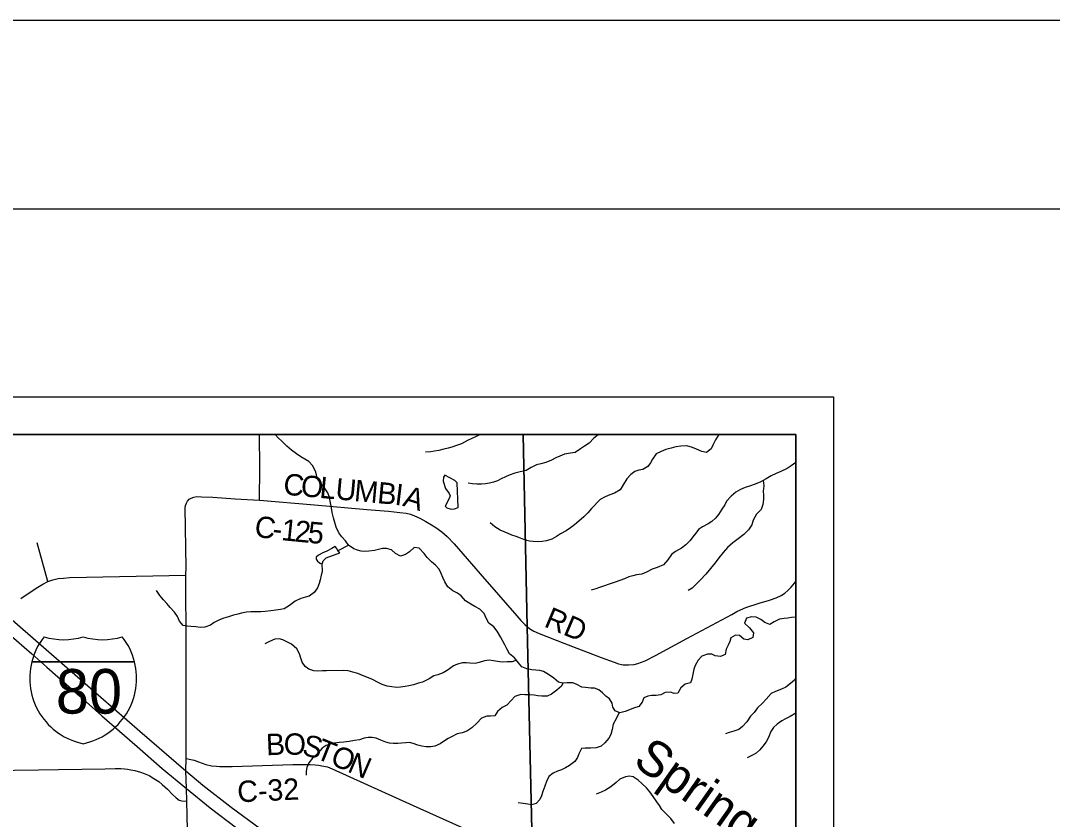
# Model space of a CAD drawing. Extents: x 0 to 34, y 0 to 22.
# Drawn here: x 6.839 to 9.582, y 19.877 to 22 of the extents above; entities that cross this region are included whole.
import ezdxf

# ---------------------------------------------------------------- set-up
doc = ezdxf.new("R2010")
doc.units = 0
for name, color, linetype in [('Default', 7, 'Continuous'), ('GM_X_County_Road', 7, 'Continuous'), ('GM_X_County_Road_Text', 7, 'Continuous'), ('GM_X_Interstate_Location', 7, 'Continuous'), ('GM_X_Interstate_Route', 7, 'Continuous'), ('GM_X_Interstate_Shield', 7, 'Continuous'), ('GM_X_Minor_Lake', 7, 'Continuous'), ('GM_X_Minor_River', 7, 'Continuous'), ('GM_X_Minor_River_Text', 7, 'Continuous'), ('GM_X_Township_Road', 7, 'Continuous'), ('SH_Border', 7, 'Continuous'), ('SH_Cut_Line', 7, 'Continuous'), ('SH_Data', 7, 'Continuous')]:
    doc.layers.add(name, color=color, linetype=linetype)

msp = doc.modelspace()

# ---------------------------------------------------------------- linework, layer by layer
at = {"layer": 'Default'}
msp.add_lwpolyline([(8.1995, 19.7718), (8.1859, 20.3892), (8.1749, 20.9), (3.2826, 20.9)], dxfattribs=at)
msp.add_lwpolyline([(8.9, 15.9304), (8.9, 20.9), (8.1749, 20.9), (8.1859, 20.3892), (8.1995, 19.7718), (8.2061, 19.4737), (8.2069, 19.4369), (8.2195, 18.875), (8.2216, 18.8361), (8.2229, 18.8136), (8.2232, 18.7798), (8.2237, 18.7271), (8.2254, 18.6464), (8.2283, 18.4271), (8.2338, 18.0126), (8.2361, 17.5877), (8.2392, 17.3521), (8.2417, 17.2403), (8.2434, 16.7876), (8.2536, 16.1438), (8.2582, 15.9227), (8.4608, 15.9241), (8.569, 15.9256)], close=True, dxfattribs=at)
at = {"layer": 'GM_X_County_Road'}
for points in [[(7.2787, 20.0387), (7.2789, 20.1292), (7.2787, 20.3326), (7.2785, 20.5259), (7.2791, 20.5462), (7.2766, 20.7047), (7.2775, 20.7109), (7.2801, 20.7176), (7.2828, 20.7229), (7.2874, 20.7279), (7.2927, 20.7309), (7.2994, 20.7335), (7.3073, 20.7349), (7.3199, 20.7346), (7.3503, 20.7335), (7.4098, 20.7293), (7.4741, 20.7253)], [(7.4741, 20.7253), (7.6206, 20.7132), (7.7597, 20.7005), (7.8166, 20.6959), (7.8475, 20.6929), (7.8636, 20.6906), (7.8754, 20.6881), (7.8864, 20.6842), (7.9007, 20.6777), (7.9159, 20.669), (7.9309, 20.6602), (7.9426, 20.6528), (7.959, 20.6411), (7.9728, 20.6291), (7.9915, 20.6098), (8.0608, 20.5294), (8.1585, 20.4179), (8.1688, 20.4057), (8.1792, 20.3948), (8.1861, 20.3886), (8.1914, 20.3848)], [(8.1914, 20.3848), (8.1944, 20.3826), (8.2036, 20.3773), (8.2179, 20.3711), (8.2827, 20.3455), (8.3819, 20.3071), (8.4165, 20.2946), (8.4287, 20.2907), (8.4407, 20.2882), (8.4552, 20.2875), (8.4699, 20.2886), (8.4799, 20.2914), (8.4997, 20.2985), (8.5268, 20.3124), (8.61, 20.3577), (8.7293, 20.422), (8.7432, 20.4296), (8.7524, 20.434), (8.7669, 20.4404), (8.8021, 20.4517), (8.8296, 20.4596), (8.8478, 20.466), (8.8604, 20.4722), (8.8706, 20.4784), (8.8786, 20.4854), (8.8871, 20.4939), (8.8961, 20.5045), (8.9, 20.5095)], [(7.2805, 19.9253), (7.2801, 19.959), (7.2785, 20.0062), (7.2787, 20.0387)], [(7.2787, 20.0387), (7.2914, 20.0361), (7.3003, 20.0341), (7.3119, 20.0299), (7.3218, 20.0262), (7.3317, 20.0232), (7.3469, 20.0198), (7.3596, 20.0183), (7.369, 20.0175), (7.4017, 20.0179), (7.563, 20.0232), (7.5984, 20.023), (7.6086, 20.0228), (7.6222, 20.0221), (7.6305, 20.0212), (7.6401, 20.0198), (7.6547, 20.0163), (7.6676, 20.011), (7.8823, 19.9136), (8.1094, 19.812), (8.1997, 19.7712), (8.2034, 19.7696)], [(6.6953, 20.0065), (6.8865, 20.0091), (6.9395, 20.0093), (7.0639, 20.0117), (7.0906, 20.0121), (7.1059, 20.0119), (7.1152, 20.0115), (7.123, 20.0107), (7.1319, 20.0091), (7.1423, 20.0073), (7.158, 20.0029), (7.1671, 19.9993), (7.1805, 19.9936), (7.1936, 19.986), (7.2061, 19.9779), (7.2157, 19.9701), (7.2296, 19.9578), (7.2431, 19.9431), (7.2522, 19.9343), (7.2602, 19.9285), (7.2676, 19.9264), (7.2805, 19.9253)], [(7.3109, 18.7479), (7.3061, 18.9361), (7.3003, 19.1331), (7.296, 19.3266), (7.2915, 19.4531), (7.2874, 19.6581), (7.2805, 19.9253)]]:
    msp.add_lwpolyline(points, dxfattribs=at)
at = {"layer": 'GM_X_Interstate_Route'}
for points in [[(6.7966, 20.4252), (6.9486, 20.2925), (7.156, 20.1111), (7.2785, 20.0062), (7.3237, 19.9679), (7.3987, 19.9098), (7.4761, 19.8527), (7.5666, 19.7895), (7.7006, 19.7055), (7.763, 19.6693)], [(6.7749, 20.3983), (6.8079, 20.3699), (6.8685, 20.317), (6.9085, 20.2814), (6.9964, 20.2046), (7.0553, 20.1519), (7.149, 20.0706), (7.2156, 20.0127), (7.2801, 19.959), (7.343, 19.9077), (7.4133, 19.8545), (7.4638, 19.8177), (7.5083, 19.7871), (7.5915, 19.7321), (7.6978, 19.6669), (7.77, 19.6256)]]:
    msp.add_lwpolyline(points, dxfattribs=at)
at = {"layer": 'GM_X_Interstate_Shield'}
for p, q in [((6.8687, 20.2958), (7.142, 20.2958)), ((7.142, 20.2958), (6.8687, 20.2958)), ((7.142, 20.2958), (6.8687, 20.2958))]:
    msp.add_line(p, q, dxfattribs=at)
for centre, start, end in [((7.0409, 20.2523), 141.669, 165.8066), ((6.9535, 20.5322), 253.0091, 286.9909), ((7.0572, 20.5322), 253.0091, 286.9909), ((6.9698, 20.2523), 14.1934, 38.331), ((7.0409, 20.2523), 165.8066, 258.463), ((6.9698, 20.2523), 281.537, 14.1934)]:
    msp.add_arc(centre, 0.1776, start, end, dxfattribs=at)
at = {"layer": 'GM_X_Minor_Lake'}
for points in [[(7.9993, 20.7717), (7.9936, 20.7774), (7.9669, 20.7919), (7.9628, 20.7869), (7.9621, 20.7763), (7.9684, 20.7566), (7.9787, 20.7434), (7.981, 20.7366), (7.9784, 20.7301), (7.968, 20.7099), (7.9722, 20.705), (7.9832, 20.702), (7.9923, 20.7029), (8.0025, 20.7056)], [(8.0025, 20.7056), (7.9993, 20.7717)], [(7.6874, 20.5852), (7.6832, 20.5894), (7.6798, 20.5973), (7.6752, 20.6022), (7.6665, 20.5972), (7.6533, 20.5898), (7.642, 20.5855), (7.6306, 20.5794), (7.6246, 20.574), (7.6247, 20.569), (7.6285, 20.563), (7.6327, 20.56), (7.6365, 20.557), (7.6418, 20.5582), (7.6433, 20.5643), (7.647, 20.5681), (7.6515, 20.5719)], [(7.6515, 20.5719), (7.6874, 20.5852)]]:
    msp.add_lwpolyline(points, dxfattribs=at)
at = {"layer": 'GM_X_Minor_River'}
for points in [[(7.6739, 20.666), (7.6711, 20.6781), (7.6676, 20.6929), (7.6659, 20.7051), (7.6632, 20.718), (7.6604, 20.7328), (7.6557, 20.7453), (7.6465, 20.7581), (7.6358, 20.7717), (7.6285, 20.7822), (7.6258, 20.7928), (7.623, 20.8027), (7.6149, 20.8178), (7.6054, 20.828), (7.5947, 20.8347), (7.584, 20.8407), (7.5726, 20.8482), (7.5588, 20.8587), (7.5466, 20.8688), (7.5332, 20.8824), (7.5237, 20.891), (7.5161, 20.9)], [(8.0611, 20.9), (8.0604, 20.8996), (8.0498, 20.8945), (8.0388, 20.8895), (8.0271, 20.8837), (8.0109, 20.8755), (7.9981, 20.8705), (7.9856, 20.8662), (7.9758, 20.8638), (7.9644, 20.8607), (7.9512, 20.8579), (7.9391, 20.8555), (7.9292, 20.8542), (7.9156, 20.853)], [(8.3761, 20.9), (8.3746, 20.8988), (8.3626, 20.8903), (8.3505, 20.8773), (8.3381, 20.8688), (8.3275, 20.8622), (8.3129, 20.8522), (8.3004, 20.8502), (8.2852, 20.8474), (8.2724, 20.8427), (8.2622, 20.8377), (8.2501, 20.8322), (8.235, 20.826), (8.2221, 20.8217), (8.21, 20.8193), (8.1964, 20.8123), (8.1825, 20.8046), (8.167, 20.801), (8.153, 20.7975), (8.1379, 20.7916), (8.1277, 20.7874), (8.1164, 20.7819), (8.1065, 20.7769), (8.0963, 20.7734), (8.0854, 20.7706), (8.0744, 20.769), (8.0645, 20.7678), (8.0516, 20.7684), (8.0399, 20.7691), (8.0285, 20.7708)], [(8.6953, 20.9), (8.6859, 20.8858), (8.68, 20.8732), (8.6744, 20.8617), (8.6623, 20.8525), (8.6498, 20.8547), (8.6357, 20.861), (8.6251, 20.8654), (8.6103, 20.8695), (8.5943, 20.8693), (8.5811, 20.8669), (8.5686, 20.8638), (8.5546, 20.8602), (8.5414, 20.8552), (8.5286, 20.8489), (8.5188, 20.8348), (8.5132, 20.8245), (8.5061, 20.8149), (8.4929, 20.8068), (8.4827, 20.8048), (8.4717, 20.8017), (8.4608, 20.7936), (8.4507, 20.7821), (8.441, 20.7664), (8.4331, 20.7534), (8.418, 20.7445), (8.4052, 20.7399), (8.3927, 20.734), (8.3795, 20.7271), (8.3566, 20.7037), (8.3472, 20.6922), (8.3363, 20.6815), (8.3228, 20.6695), (8.3111, 20.6599), (8.3006, 20.6519), (8.2893, 20.6438), (8.2745, 20.6356), (8.2636, 20.6291), (8.2508, 20.6221), (8.2372, 20.6178), (8.2251, 20.6158), (8.2126, 20.6145), (8.2016, 20.6152), (8.1917, 20.6162), (8.1811, 20.6196), (8.1681, 20.6244), (8.156, 20.6288), (8.1449, 20.6329), (8.1354, 20.6366), (8.1244, 20.6414), (8.1134, 20.6459), (8.1, 20.6549), (8.0874, 20.665)], [(8.9, 20.8256), (8.8874, 20.817), (8.8765, 20.8101), (8.8603, 20.8016), (8.8471, 20.7961), (8.8346, 20.7903), (8.821, 20.7822), (8.8052, 20.7737), (8.7893, 20.7667), (8.7791, 20.7636), (8.7647, 20.7589), (8.7527, 20.7538), (8.7402, 20.7469), (8.7278, 20.7365), (8.7154, 20.7231), (8.7109, 20.7131), (8.7031, 20.702), (8.6945, 20.6871), (8.6866, 20.6776), (8.6768, 20.6684), (8.667, 20.6629), (8.6519, 20.6548), (8.6414, 20.6475), (8.6339, 20.6376), (8.6264, 20.628), (8.6193, 20.6184), (8.6076, 20.6065), (8.5959, 20.5977), (8.5801, 20.5895), (8.5692, 20.5807), (8.5598, 20.5669), (8.5482, 20.5539), (8.5312, 20.5465), (8.5176, 20.5422), (8.5025, 20.5337), (8.49, 20.5287), (8.476, 20.5266), (8.4662, 20.5246), (8.4556, 20.5219), (8.4439, 20.5164), (8.4322, 20.5121), (8.4197, 20.5078), (8.4034, 20.502), (8.3883, 20.4969), (8.3781, 20.493), (8.3679, 20.4895), (8.3558, 20.4863)], [(8.8132, 20.778), (8.8147, 20.7639), (8.813, 20.7498), (8.8134, 20.7384), (8.8135, 20.7274), (8.8118, 20.7137), (8.8077, 20.7004), (8.7953, 20.6881), (8.7863, 20.6724), (8.7827, 20.6603), (8.7744, 20.6465), (8.7613, 20.6338), (8.7462, 20.6227), (8.7327, 20.6119), (8.7184, 20.6), (8.7063, 20.5866), (8.6955, 20.5724), (8.6854, 20.559), (8.673, 20.5441), (8.6602, 20.5288), (8.6463, 20.5138), (8.6369, 20.5038), (8.6245, 20.4919), (8.614, 20.4858)], [(8.6996, 20.3099), (8.6856, 20.3117), (8.6761, 20.3158), (8.6647, 20.3164), (8.6503, 20.3106), (8.6398, 20.2998), (8.6324, 20.2865), (8.629, 20.2765), (8.6257, 20.2632), (8.6236, 20.2495), (8.6195, 20.24), (8.6055, 20.2368), (8.5942, 20.2264), (8.5864, 20.2127), (8.5761, 20.2118), (8.5666, 20.2152), (8.5526, 20.2143), (8.5413, 20.2085), (8.5288, 20.2064), (8.5159, 20.2063), (8.5061, 20.2047), (8.4959, 20.2004), (8.4911, 20.189), (8.4824, 20.1775), (8.4685, 20.1728), (8.4579, 20.1685), (8.4458, 20.1639), (8.4318, 20.1603), (8.4192, 20.1655), (8.4135, 20.1753), (8.4119, 20.1863), (8.4049, 20.1973), (8.395, 20.2044), (8.3855, 20.2131), (8.3759, 20.2213), (8.3645, 20.2254), (8.3547, 20.2261), (8.341, 20.2274), (8.3311, 20.2289), (8.3178, 20.2356), (8.3068, 20.2404), (8.2916, 20.2403), (8.2802, 20.2394), (8.2689, 20.2416), (8.2566, 20.2521), (8.2421, 20.2622), (8.2288, 20.2701), (8.2193, 20.2726), (8.2083, 20.2741), (8.1977, 20.2747), (8.1848, 20.2769), (8.1718, 20.2824), (8.1623, 20.293), (8.1519, 20.3066), (8.1389, 20.3167), (8.1312, 20.3303), (8.1258, 20.3413), (8.1151, 20.3625), (8.1062, 20.3776), (8.0966, 20.3889), (8.0833, 20.3982), (8.0763, 20.4119), (8.0713, 20.4244), (8.0595, 20.436), (8.0465, 20.4431), (8.0355, 20.4491), (8.0221, 20.4581), (8.0102, 20.4716), (8.0007, 20.4784), (7.9878, 20.4847), (7.9748, 20.4949), (7.9671, 20.5088), (7.9617, 20.5202), (7.9574, 20.5304), (7.9516, 20.5418), (7.9417, 20.5531), (7.9314, 20.5617), (7.9199, 20.5734), (7.9119, 20.5839), (7.8985, 20.5979), (7.8856, 20.5993), (7.8724, 20.5885), (7.8626, 20.5812), (7.849, 20.5769), (7.836, 20.584), (7.825, 20.5934), (7.8113, 20.597), (7.8011, 20.5966), (7.7901, 20.5942), (7.7795, 20.5918), (7.7651, 20.5898), (7.7545, 20.5889), (7.7439, 20.5903), (7.7344, 20.5925), (7.7245, 20.5958), (7.7111, 20.6063), (7.7031, 20.6173), (7.6928, 20.6282), (7.6847, 20.6391), (7.6781, 20.6535), (7.6739, 20.666)], [(7.7116, 20.606), (7.6826, 20.5907)], [(7.6402, 20.5578), (7.6405, 20.5354), (7.6383, 20.5258), (7.6357, 20.5137), (7.6324, 20.5038), (7.6284, 20.4927), (7.6197, 20.4797), (7.6062, 20.4704), (7.5963, 20.4677), (7.5839, 20.4645), (7.5691, 20.4572), (7.5541, 20.4453), (7.5398, 20.4364), (7.5299, 20.4348), (7.5174, 20.4327), (7.5042, 20.4311), (7.489, 20.4298), (7.478, 20.4289), (7.4644, 20.4288), (7.4511, 20.4283), (7.4394, 20.4274), (7.4265, 20.4254), (7.4167, 20.4227), (7.4053, 20.4195), (7.3913, 20.4156), (7.3792, 20.412), (7.3679, 20.4078), (7.354, 20.4004), (7.3434, 20.3935), (7.3287, 20.388), (7.3162, 20.3875), (7.3048, 20.3885), (7.2919, 20.3896), (7.2816, 20.3902), (7.2714, 20.392), (7.2618, 20.4037), (7.256, 20.4162), (7.2483, 20.4279), (7.2369, 20.4399), (7.2277, 20.4505), (7.2189, 20.4603), (7.2093, 20.4724), (7.2005, 20.4852)], [(8.9, 20.4146), (8.8886, 20.4132), (8.8788, 20.4115), (8.869, 20.4114), (8.8561, 20.409), (8.8425, 20.4021), (8.8304, 20.3951), (8.8171, 20.4003), (8.8068, 20.4082), (8.7943, 20.4145), (8.7821, 20.4156), (8.7689, 20.412), (8.7629, 20.399), (8.7763, 20.3866), (8.787, 20.373), (8.7852, 20.3609), (8.7724, 20.3547), (8.7618, 20.3561), (8.7496, 20.3662), (8.7397, 20.3669), (8.7269, 20.3599), (8.7247, 20.3497), (8.7202, 20.3401), (8.7146, 20.3298), (8.7121, 20.315), (8.6996, 20.3099)], [(8.1571, 20.2998), (8.146, 20.2959), (8.1323, 20.2954), (8.119, 20.2949), (8.1069, 20.2966), (8.0963, 20.2988), (8.0845, 20.2999), (8.0724, 20.2986), (8.0584, 20.2939), (8.0471, 20.2915), (8.0334, 20.2925), (8.0239, 20.2932), (8.0141, 20.2931), (8.0004, 20.2899), (7.9899, 20.2853), (7.9756, 20.2745), (7.9624, 20.2664), (7.948, 20.2613), (7.9378, 20.2589), (7.925, 20.2505), (7.9076, 20.2419), (7.8966, 20.2388), (7.8838, 20.2349), (7.8709, 20.2317), (7.8611, 20.2301), (7.849, 20.2281), (7.8387, 20.228), (7.8255, 20.229), (7.8133, 20.2312), (7.8, 20.236), (7.7894, 20.2412), (7.7745, 20.249), (7.7597, 20.255), (7.7483, 20.2598), (7.7357, 20.2646), (7.7224, 20.2687), (7.7095, 20.2716), (7.6981, 20.2726), (7.6526, 20.2722), (7.6416, 20.2717), (7.628, 20.2708), (7.6181, 20.2715), (7.6048, 20.2763), (7.5953, 20.2834), (7.5876, 20.2951), (7.5841, 20.3053), (7.5802, 20.3175), (7.5729, 20.3303), (7.5588, 20.3427), (7.5489, 20.3483), (7.5363, 20.3539), (7.526, 20.3568), (7.5147, 20.3563), (7.5003, 20.3501), (7.4879, 20.3439)], [(8.9, 20.2532), (8.8958, 20.2472), (8.8856, 20.238), (8.8736, 20.2287), (8.8615, 20.2229), (8.8456, 20.2174), (8.8339, 20.2113), (8.8212, 20.1967), (8.811, 20.1856), (8.7982, 20.1733), (8.7889, 20.1614), (8.7791, 20.1511), (8.7697, 20.1365), (8.7581, 20.1235), (8.7483, 20.1162), (8.7351, 20.1115), (8.7226, 20.1084), (8.7128, 20.1048)], [(8.2807, 20.2394), (8.2773, 20.2314), (8.2645, 20.2203), (8.2502, 20.2102), (8.2388, 20.2048), (8.2244, 20.2043), (8.2142, 20.2057), (8.204, 20.2075), (8.193, 20.2082), (8.1793, 20.2084), (8.1687, 20.2091), (8.1532, 20.204), (8.1427, 20.1933), (8.1314, 20.1806), (8.1189, 20.1744), (8.1065, 20.1637), (8.0998, 20.1526), (8.0881, 20.1517), (8.0782, 20.1516), (8.0642, 20.1458), (8.0518, 20.1327), (8.0387, 20.1205), (8.0255, 20.1116), (8.013, 20.1073), (7.9998, 20.1041), (7.9862, 20.0975), (7.976, 20.0921), (7.9662, 20.0856), (7.9541, 20.0782), (7.9398, 20.0713), (7.9296, 20.0696), (7.9171, 20.0699), (7.9053, 20.0717), (7.895, 20.0746), (7.8825, 20.0787), (7.873, 20.0813), (7.8631, 20.0808), (7.8518, 20.0799), (7.8419, 20.0787), (7.8306, 20.0786), (7.8196, 20.08), (7.8097, 20.0826), (7.7967, 20.0877), (7.7846, 20.093), (7.7739, 20.0951), (7.7633, 20.095), (7.7527, 20.093), (7.7399, 20.0887), (7.7266, 20.0863), (7.7126, 20.0843), (7.6986, 20.0826), (7.6861, 20.081), (7.6725, 20.0793), (7.6623, 20.077), (7.6513, 20.0731), (7.6411, 20.0665), (7.6299, 20.0542), (7.6152, 20.0397), (7.6051, 20.0274), (7.5995, 20.0152), (7.5981, 20.0053), (7.5978, 19.995)], [(8.4302, 20.161), (8.4225, 20.1446), (8.4142, 20.1301), (8.4117, 20.116), (8.408, 20.1027), (8.4024, 20.0928), (8.3923, 20.0805), (8.3821, 20.0721), (8.3689, 20.0674), (8.3541, 20.0665), (8.3401, 20.0667), (8.3303, 20.0655), (8.3232, 20.0514), (8.3191, 20.0414), (8.312, 20.0311), (8.2981, 20.02), (8.2871, 20.0138), (8.2773, 20.0091), (8.2664, 20.0052), (8.2543, 20.0002), (8.243, 19.9909), (8.2366, 19.9776), (8.2322, 19.965), (8.227, 19.9513), (8.2241, 19.9398), (8.2192, 19.9303), (8.2091, 19.9196), (8.197, 19.9156), (8.1875, 19.9175), (8.1746, 19.9192), (8.1617, 19.921)], [(8.9, 20.1591), (8.8845, 20.1509), (8.8724, 20.1444), (8.8626, 20.139), (8.8505, 20.1305), (8.8404, 20.1216), (8.8336, 20.1106), (8.8273, 20.0945), (8.8206, 20.0831), (8.812, 20.072), (8.8045, 20.062), (8.794, 20.0532), (8.7842, 20.0474), (8.7702, 20.0404)], [(8.5776, 19.8665), (8.5673, 19.8793), (8.5573, 19.8902), (8.5436, 19.9034), (8.5374, 19.914), (8.5305, 19.9238), (8.5205, 19.9377), (8.5117, 19.9506), (8.5029, 19.9607), (8.4903, 19.9724), (8.4807, 19.981), (8.4678, 19.99), (8.4575, 19.9915), (8.4469, 19.9898), (8.4318, 19.984), (8.422, 19.9752), (8.4077, 19.964), (8.3942, 19.9544), (8.3824, 19.9497), (8.3692, 19.9439)]]:
    msp.add_lwpolyline(points, dxfattribs=at)
at = {"layer": 'GM_X_Township_Road'}
msp.add_line((6.9115, 20.5095), (6.8834, 20.6118), dxfattribs=at)
for points in [[(7.4741, 20.7253), (7.475, 20.8109), (7.4745, 20.9)], [(6.8394, 20.4642), (6.8808, 20.4916), (6.8977, 20.5019), (6.9115, 20.5095), (6.9248, 20.5139), (6.9389, 20.5169), (6.9534, 20.5185), (6.9695, 20.5197), (7.2785, 20.5259)]]:
    msp.add_lwpolyline(points, dxfattribs=at)
at = {"layer": 'SH_Border'}
msp.add_lwpolyline([(1.5, 21.5), (33.5, 21.5), (33.5, 0.5), (1.5, 0.5)], close=True, dxfattribs=at)
at = {"layer": 'SH_Cut_Line'}
for points in [[(0, 0), (34, 0), (34, 22), (0, 22)], [(3.2807, 14.1), (8.9, 14.1), (8.9, 20.9), (3.2826, 20.9), (3.2843, 20.6124), (3.2845, 20.5998), (3.2888, 19.8918), (3.2901, 19.68), (3.2904, 19.1173), (3.2907, 18.4315), (3.2837, 17.3796), (3.2835, 17.0107), (3.2832, 16.3898), (3.2829, 15.8433), (3.2815, 15.7537), (3.2811, 15.7294), (3.2832, 14.8896), (3.2841, 14.501), (3.2822, 14.2781), (3.2808, 14.1155)]]:
    msp.add_lwpolyline(points, close=True, dxfattribs=at)
at = {"layer": 'SH_Data'}
for p, q in [((2, 21), (9, 21)), ((9, 21), (9, 14)), ((2.1, 20.9), (8.9, 20.9)), ((8.9, 20.9), (8.9, 14.1))]:
    msp.add_line(p, q, dxfattribs=at)

# ---------------------------------------------------------------- texts
at = {"layer": 'GM_X_County_Road_Text'}
for s, height, rotation, p in [('C', 0.0568, 354.7784, (7.5358, 20.7405)), ('O', 0.0568, 354.7762, (7.5823, 20.7363)), ('L', 0.0568, 354.7772, (7.6321, 20.7317)), ('U', 0.0568, 354.7762, (7.6744, 20.7279)), ('M', 0.0568, 354.7767, (7.7242, 20.7233)), ('B', 0.0568, 354.7119, (7.7856, 20.7177)), ('I', 0.0568, 353.0357, (7.8316, 20.7135)), ('A', 0.0568, 342.8461, (7.8522, 20.7112)), ('C', 0.0568, 351.7954, (7.4584, 20.629)), ('1', 0.0568, 354.1156, (7.5303, 20.6195)), ('2', 0.0568, 354.6479, (7.5657, 20.6158)), ('5', 0.0568, 354.7997, (7.6007, 20.6125)), ('-', 0.0568, 353.5661, (7.5065, 20.6221)), ('RD', 0.05682, 337.1916, (8.2278, 20.3906)), ('B', 0.0568, 2.2761, (7.4924, 20.0473)), ('O', 0.0568, 359.3078, (7.5382, 20.0492)), ('S', 0.0568, 346.3636, (7.5848, 20.049)), ('T', 0.0568, 338.0434, (7.62, 20.0406)), ('O', 0.0568, 336.7765, (7.6591, 20.0248)), ('N', 0.0568, 336.7617, (7.7051, 20.0051)), ('C-32', 0.05682, 2.7424, (7.4163, 19.9222))]:
    msp.add_text(s, height=height, rotation=rotation, dxfattribs=at).set_placement(p)
at = {"layer": 'GM_X_Interstate_Location'}
for s in ['-', '.', ',']:
    msp.add_text(s, height=0.000189, dxfattribs=at).set_placement((7.0053, 20.2203))
msp.add_text('80', height=0.000189, rotation=0, dxfattribs=at).set_placement((6.9666, 20.1811))
at = {"layer": 'GM_X_Interstate_Shield'}
msp.add_text('80', height=0.11837, dxfattribs=at).set_placement((6.9326, 20.1582))
at = {"layer": 'GM_X_Minor_River_Text'}
msp.add_text('Spring', height=0.09475, rotation=324.8242, dxfattribs=at).set_placement((8.4634, 20.0235))

doc.saveas('drawing.dxf')
